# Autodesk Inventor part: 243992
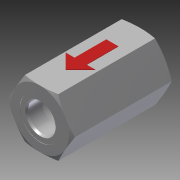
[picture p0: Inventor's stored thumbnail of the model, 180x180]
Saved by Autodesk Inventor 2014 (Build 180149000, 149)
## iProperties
Shininess: 20.0
Length Units: 11272
Angle Units: 11279
Time Units: 11290
Mass Units: 11286
Length Display Precision: 3
Angle Display Precision: 2
Company: Autodesk, Inc.
Created: 2002-07
Part Number: 243992
Material: Steel, Mild
Description: VALVE, CHECK
Document SubType Name: Modeling
Designer: Autodesk, Inc.
Density: 7.86 g/cm^3
Mass: 5026.46 g
Surface Area: 765.266 cm^2
Volume: 639.499 cm^3
Appearance: Steel
Density: 0.0
Volumn: 0.0
Area: 0.0
PropertySet Name: Model Information
Control State: 0
Master: False
Checked Out: False
Last Check In By: JT
Last Check In Date: 2003-06-20
Title: VALVE, CHECK
Author: Autodesk, Inc.
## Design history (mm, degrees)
sketch "Sketch1"
  geometry: L1 (-23.83, -41.275)-(-47.66, 0); L2 (-47.66, 0)-(-23.83, 41.275); L3 (-23.83, 41.275)-(23.83, 41.275); L4 (23.83, 41.275)-(47.66, 0); L5 (47.66, 0)-(23.83, -41.275); L6 (23.83, -41.275)-(-23.83, -41.275); 2 further points
  constraints: 12 end point, 1 coincident, 1 horizontal, 11 other
  dimensions: "d5" = 82.55 distance between parallel lines of L6 L3
extrude "Extrusion2" new body sketch "Sketch1" stored distance "d6" = 142.875; taper "d7" = 0 deg
sketch "Sketch2"
  geometry: L1 (-23.83, 71.438)-(-23.83, -71.438) reference; L2 (23.83, -71.438)-(23.83, 71.438) reference; L3 (0.739, 33.856)-(21.821, 12.775); L4 (21.821, 12.775)-(9.285, 12.775); L5 (9.285, 12.775)-(9.285, -32.6); L6 (9.285, -32.6)-(-7.806, -32.6); L7 (-7.806, -32.6)-(-7.806, 12.775); L8 (-7.806, 12.775)-(-20.342, 12.775); L9 (-20.342, 12.775)-(0.739, 33.856); L10 (0.739, -32.6)-(0.739, 33.856)
  constraints: 16 end point, 6 perpendicular, 3 equal length, 1 midpoint, 1 vertical
extrude "Extrusion3" join sketch "Sketch2" stored distance "d8" = 83.566; taper "d9" = 0 deg
sketch "Sketch3"
  geometry: L1 (-41.275, 71.438)-(0, 71.438) reference; L2 (0, 71.438)-(41.275, 71.438) reference; L3 (0, -71.438)-(-41.275, -71.438) reference; L4 (41.275, -71.438)-(0, -71.438) reference; L5 (-28.829, 71.438)-(-28.829, 70.93); L6 (-28.829, 70.93)-(-21.755, 70.93); L7 (-21.755, 70.93)-(-20.638, 67.577); L8 (-20.638, 67.577)-(-20.638, 47.917); L9 (-20.638, 47.917)-(-15.875, 43.155); L10 (-15.875, 43.155)-(-15.875, 18.789); L11 (-15.875, 18.789)-(-30.162, 18.789); L12 (-30.162, 18.789)-(-30.162, -18.789); L13 (-30.162, -18.789)-(-15.875, -18.789); L14 (-15.875, -18.789)-(-15.875, -43.155); L15 (-15.875, -43.155)-(-20.638, -47.917); L16 (-20.638, -47.917)-(-20.638, -67.577); L17 (-20.638, -67.577)-(-21.755, -70.93); L18 (-21.755, -70.93)-(-28.829, -70.93); L19 (-28.829, -70.93)-(-28.829, -71.438); L20 (0, 71.438)-(0, -71.438); 3 further points
  constraints: 32 end point, 9 parallel, 6 equal length, 5 point on line, 4 vertical alignment, 3 perpendicular, 4 other
  dimensions: "d11" = 0.508 distance between parallel lines of L1 L6; "d12" = 57.658 diameter of L5.start L20; "d13" = 41.275 diameter of L8 L20; "d14" = 43.5102 diameter of L6.end L20; "d15" = 3.3528 vertical distance of L6.end L7.end; "d16" = 23.0124 distance from line of L8.end L6; "d17" = 45 deg angle of L8 L9; "d18" = 31.75 diameter of L10 L20
revolve "Revolution1" sketch "Sketch3" stored, may be unused: angle "d19" = 90 deg
sketch "Sketch4"
  geometry: L1 (-23.83, 71.438)-(-47.66, 71.438) reference; L2 (23.83, 71.438)-(-23.83, 71.438) reference; L3 (47.66, 71.438)-(23.83, 71.438) reference; L4 (-47.66, 71.438)-(-47.66, -71.438) reference; L5 (-23.83, 71.438)-(-23.83, -71.438) reference; L6 (-47.66, 69.113)-(-41.275, 71.438); L7 (-23.83, -71.438)-(-47.66, -71.438) reference; L8 (-41.275, -71.438)-(-47.66, -69.113); L9 (0, -100.012)-(0, 100.012) reference; 1 further point
  constraints: 4 end point, 4 point on line, 1 vertical alignment
  dimensions: "d20" = 41.275 horizontal distance of point (0, 0) L6.end; "d21" = 20 deg angle of L1 L6; "d22" = 20 deg angle of L7 L8
revolve "Revolution2" sketch "Sketch4" stored, may be unused: angle "d23" = 90 deg
body "Solid1"
